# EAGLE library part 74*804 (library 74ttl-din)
Hex NAND driver
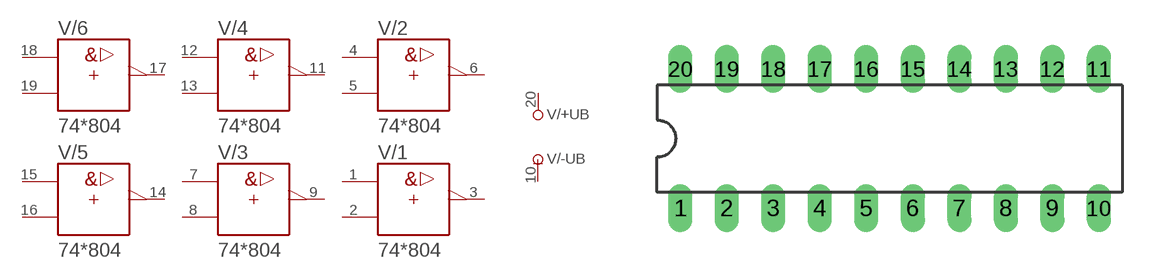
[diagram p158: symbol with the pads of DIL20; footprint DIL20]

Designator prefix V; gates /+UB=+UB /-UB=-UB /1=804 /2=804 /3=804 /4=804 /5=804 /6=804

## 74804N  [DIL20]
1  /1:A  in
2  /1:B  in
3  /1:Y  out
4  /2:A  in
5  /2:B  in
6  /2:Y  out
7  /3:A  in
8  /3:B  in
9  /3:Y  out
10  /-UB:-UB  pwr
11  /4:Y  out
12  /4:A  in
13  /4:B  in
14  /5:Y  out
15  /5:A  in
16  /5:B  in
17  /6:Y  out
18  /6:A  in
19  /6:B  in
20  /+UB:+UB  pwr

## Footprint DIL20 (pad centres in mm)
Dual In Line Package
drill 0.813 long: 1 -11.43,-3.81; 2 -8.89,-3.81; 3 -6.35,-3.81; 4 -3.81,-3.81; 5 -1.27,-3.81; 6 1.27,-3.81; 7 3.81,-3.81; 8 6.35,-3.81; 9 8.89,-3.81; 10 11.43,-3.81; 11 11.43,3.81; 12 8.89,3.81; 13 6.35,3.81; 14 3.81,3.81; 15 1.27,3.81; 16 -1.27,3.81; 17 -3.81,3.81; 18 -6.35,3.81; 19 -8.89,3.81; 20 -11.43,3.81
